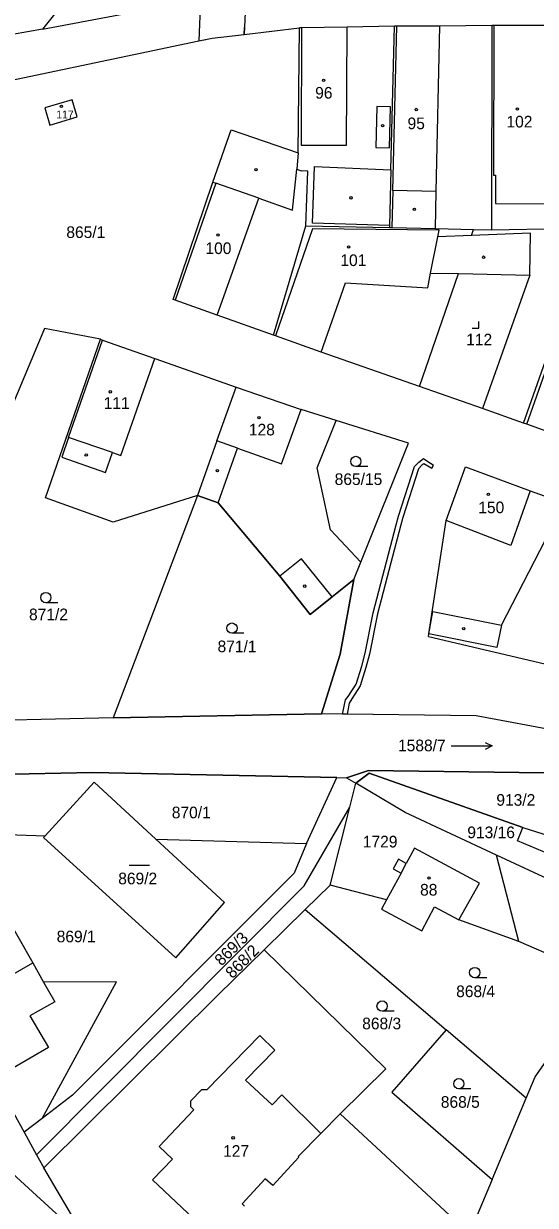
# Model space of a CAD drawing. Extents: x -801826 to -800592, y -1032871 to -1031813.
# Drawn here: x -801007.9 to -800933.1, y -1032553.2 to -1032380.8 of the extents above; entities that cross this region are included whole.
import ezdxf

# ---------------------------------------------------------------- set-up
doc = ezdxf.new("R2010")
doc.units = 0
for name, color, linetype in [('Vrstva 1', 7, 'Continuous'), ('Vrstva 18', 7, 'Continuous'), ('Vrstva 19', 7, 'Continuous'), ('Vrstva 25', 7, 'Continuous'), ('Vrstva 26', 7, 'Continuous'), ('Vrstva 27', 7, 'Continuous'), ('Vrstva 4', 7, 'Continuous')]:
    doc.layers.add(name, color=color, linetype=linetype)

msp = doc.modelspace()

# ---------------------------------------------------------------- linework, layer by layer
at = {"layer": 'Vrstva 1'}
for p, q in [((-800988.54, -1032360.72), (-801005.11, -1032381.61)), ((-801005.11, -1032381.61), (-800982.02, -1032377.22)), ((-801005.11, -1032381.61), (-801018.93, -1032384.07)), ((-800980.34, -1032382.92), (-800975.67, -1032382.37)), ((-800975.67, -1032382.37), (-800967.59, -1032381.42)), ((-800967.74, -1032399.64), (-800967.59, -1032381.42)), ((-800967.29, -1032381.42), (-800967.59, -1032381.42)), ((-800960.59, -1032381.31), (-800967.29, -1032381.42)), ((-800953.67, -1032381.14), (-800960.59, -1032381.31)), ((-800954.21, -1032402.14), (-800953.67, -1032381.14)), ((-800953.37, -1032381.15), (-800953.67, -1032381.14)), ((-800947.06, -1032381.14), (-800953.37, -1032381.15)), ((-800939.48, -1032381.05), (-800947.06, -1032381.14)), ((-800939.48, -1032381.05), (-800939.55, -1032410.87)), ((-800939.18, -1032381.05), (-800939.48, -1032381.05)), ((-800931.09, -1032381.06), (-800939.18, -1032381.05)), ((-801034.47, -1032394.27), (-800982.25, -1032383.32)), ((-800982.25, -1032383.32), (-800980.34, -1032382.92)), ((-801000.76, -1032391.91), (-801004.77, -1032393.09)), ((-801000.02, -1032394.4), (-801000.76, -1032391.91)), ((-801004.77, -1032393.09), (-801004.05, -1032395.59)), ((-801004.05, -1032395.59), (-801000.02, -1032394.4)), ((-800980.21, -1032403.9), (-800977.53, -1032396.3)), ((-800977.53, -1032396.3), (-800967.74, -1032399.64)), ((-800967.74, -1032399.64), (-800967.98, -1032402.01)), ((-800967.98, -1032402.01), (-800967.31, -1032402.26)), ((-800966.33, -1032402.33), (-800967.31, -1032402.26)), ((-800966.66, -1032410.29), (-800966.33, -1032402.33)), ((-800954.21, -1032402.14), (-800954.4, -1032410.24)), ((-800986.01, -1032421.04), (-800980.21, -1032403.9)), ((-800971.37, -1032426.24), (-800966.66, -1032410.29)), ((-800966.66, -1032410.29), (-800954.41, -1032410.53)), ((-800954.4, -1032410.24), (-800954.41, -1032410.53)), ((-800954.41, -1032410.53), (-800954.06, -1032410.54)), ((-800954.06, -1032410.54), (-800947.71, -1032410.69)), ((-800947.71, -1032410.69), (-800942.15, -1032410.81)), ((-800942.45, -1032411.68), (-800942.15, -1032410.81)), ((-800933.82, -1032411.34), (-800942.45, -1032411.68)), ((-800942.15, -1032410.81), (-800939.55, -1032410.87)), ((-800939.55, -1032410.87), (-800925.85, -1032410.64)), ((-800933.94, -1032417.46), (-800933.82, -1032411.34)), ((-800950.04, -1032433.72), (-800944.37, -1032417.25)), ((-800944.37, -1032417.25), (-800933.94, -1032417.46)), ((-800933.94, -1032417.46), (-800940.86, -1032436.95)), ((-800985.73, -1032421.14), (-800986.01, -1032421.04)), ((-800979.58, -1032423.33), (-800985.73, -1032421.14)), ((-800971.37, -1032426.24), (-800979.58, -1032423.33)), ((-801004.8, -1032425.27), (-801028.52, -1032481.63)), ((-800996.61, -1032426.84), (-801004.8, -1032425.27)), ((-801004.67, -1032449.96), (-800996.61, -1032426.84)), ((-800996.61, -1032426.84), (-800996.33, -1032426.94)), ((-800996.33, -1032426.94), (-800988.7, -1032429.66)), ((-800971.09, -1032426.34), (-800971.37, -1032426.24)), ((-800964.38, -1032428.69), (-800971.09, -1032426.34)), ((-800934.84, -1032439.06), (-800930.45, -1032426.67)), ((-800950.04, -1032433.72), (-800964.38, -1032428.69)), ((-800988.7, -1032429.66), (-800976.84, -1032433.83)), ((-800979.63, -1032441.65), (-800976.84, -1032433.83)), ((-800976.84, -1032433.83), (-800967.32, -1032437.08)), ((-800940.86, -1032436.95), (-800950.04, -1032433.72)), ((-800962.22, -1032438.68), (-800967.32, -1032437.08)), ((-800934.84, -1032439.06), (-800940.86, -1032436.95)), ((-800964.97, -1032445.61), (-800962.22, -1032438.68)), ((-800951.67, -1032441.99), (-800962.22, -1032438.68)), ((-800934.37, -1032439.23), (-800934.84, -1032439.06)), ((-800927.67, -1032441.66), (-800934.37, -1032439.23)), ((-800979.63, -1032441.65), (-800982.48, -1032449.6)), ((-800958.63, -1032459.35), (-800951.67, -1032441.99)), ((-800963.05, -1032454.65), (-800964.97, -1032445.61)), ((-800946.15, -1032453.29), (-800943.33, -1032445.44)), ((-800943.33, -1032445.44), (-800933.9, -1032448.93)), ((-800982.48, -1032449.6), (-800994.78, -1032453.49)), ((-800982.48, -1032449.6), (-800994.76, -1032482.06)), ((-800982.48, -1032449.6), (-800994.76, -1032482.06)), ((-800982.48, -1032449.6), (-800979.46, -1032450.68)), ((-800979.46, -1032450.68), (-800982.48, -1032449.6)), ((-800933.9, -1032448.93), (-800928.9, -1032450.72)), ((-800994.78, -1032453.49), (-801004.67, -1032449.96)), ((-800979.46, -1032450.68), (-800970.46, -1032461.4)), ((-800970.46, -1032461.4), (-800979.46, -1032450.68)), ((-800938.09, -1032468.54), (-800928.9, -1032450.72)), ((-800958.63, -1032459.35), (-800963.05, -1032454.65)), ((-800948.66, -1032469.78), (-800946.15, -1032453.29)), ((-800959.63, -1032461.86), (-800958.63, -1032459.35)), ((-800970.46, -1032461.4), (-800966.01, -1032466.96)), ((-800966.01, -1032466.96), (-800970.46, -1032461.4)), ((-800962.82, -1032464.41), (-800959.63, -1032461.86)), ((-800959.63, -1032461.86), (-800962.82, -1032464.41)), ((-800959.63, -1032461.86), (-800961.65, -1032472.78)), ((-800961.65, -1032472.78), (-800959.63, -1032461.86)), ((-800966.01, -1032466.96), (-800962.82, -1032464.41)), ((-800962.82, -1032464.41), (-800966.01, -1032466.96)), ((-800938.09, -1032468.54), (-800938.74, -1032471.78)), ((-800948.73, -1032470.17), (-800948.66, -1032469.78)), ((-800948.73, -1032470.17), (-800927.61, -1032475.17)), ((-800938.74, -1032471.78), (-800948.66, -1032469.78)), ((-800961.65, -1032472.78), (-800964.35, -1032481.48)), ((-800964.35, -1032481.48), (-800961.65, -1032472.78)), ((-800994.76, -1032482.06), (-801024.5, -1032482.76)), ((-800994.76, -1032482.06), (-801024.5, -1032482.76)), ((-800964.35, -1032481.48), (-800994.76, -1032482.06)), ((-800994.76, -1032482.06), (-800964.35, -1032481.48)), ((-800964.35, -1032481.48), (-800994.76, -1032482.06)), ((-800941.77, -1032481.76), (-800964.35, -1032481.48)), ((-800961.28, -1032481.52), (-800964.35, -1032481.48)), ((-800941.77, -1032481.76), (-800960.62, -1032481.53)), ((-800920.07, -1032485.78), (-800941.77, -1032481.76)), ((-800920.07, -1032485.78), (-800941.77, -1032481.76)), ((-800997.78, -1032490.01), (-801020.2, -1032490.51)), ((-801020.2, -1032490.51), (-800997.78, -1032490.01)), ((-800962.1, -1032490.76), (-800997.78, -1032490.01)), ((-800997.78, -1032490.01), (-800962.1, -1032490.76)), ((-800966.57, -1032500.41), (-800962.1, -1032490.76)), ((-800962.1, -1032490.76), (-800960.71, -1032490.83)), ((-800962.1, -1032490.76), (-800960.71, -1032490.83)), ((-800957.47, -1032489.74), (-800960.71, -1032490.83)), ((-800957.47, -1032489.74), (-800960.71, -1032490.83)), ((-800960.71, -1032490.83), (-800957.47, -1032489.74)), ((-800960.71, -1032490.83), (-800959.34, -1032491.58)), ((-800960.71, -1032490.83), (-800959.34, -1032491.58)), ((-800957.38, -1032490.12), (-800959.34, -1032491.58)), ((-800959.34, -1032491.58), (-800957.38, -1032490.12)), ((-800931.84, -1032490.09), (-800957.47, -1032489.74)), ((-800931.84, -1032490.09), (-800957.47, -1032489.74)), ((-800957.47, -1032489.74), (-800931.84, -1032490.09)), ((-800934.97, -1032498.07), (-800957.38, -1032490.12)), ((-800957.38, -1032490.12), (-800934.97, -1032498.07)), ((-800997.57, -1032491.42), (-801004.72, -1032499.25)), ((-800988.55, -1032499.75), (-800997.57, -1032491.42)), ((-800960.22, -1032495.07), (-800959.34, -1032491.58)), ((-800952.14, -1032495.84), (-800959.34, -1032491.58)), ((-800966.87, -1032506.55), (-800960.22, -1032495.07)), ((-800963.1, -1032506.46), (-800960.22, -1032495.07)), ((-800938.81, -1032502.08), (-800952.14, -1032495.84)), ((-801017.33, -1032498.87), (-801006.53, -1032517.81)), ((-801017.33, -1032498.87), (-801004.72, -1032499.25)), ((-801004.72, -1032499.25), (-801004.96, -1032499.52)), ((-801004.96, -1032499.52), (-800985.65, -1032517.05)), ((-800935.72, -1032499.98), (-800934.97, -1032498.07)), ((-800934.97, -1032498.07), (-800914.08, -1032504.56)), ((-800934.97, -1032498.07), (-800914.08, -1032504.56)), ((-800978.54, -1032508.99), (-800988.55, -1032499.75)), ((-800988.55, -1032499.75), (-800966.57, -1032500.41)), ((-800966.57, -1032500.41), (-800968.36, -1032504.73)), ((-800950.77, -1032501.05), (-800951.97, -1032503.29)), ((-800941.3, -1032506.19), (-800950.77, -1032501.05)), ((-800917.44, -1032507.8), (-800935.72, -1032499.98)), ((-800953.11, -1032502.68), (-800953.88, -1032504.08)), ((-800951.97, -1032503.29), (-800953.11, -1032502.68)), ((-800935.54, -1032514.69), (-800938.81, -1032502.08)), ((-800918.13, -1032511.75), (-800938.81, -1032502.08)), ((-800968.36, -1032504.73), (-801000.73, -1032537.11)), ((-800952.73, -1032504.7), (-800954.86, -1032508.62)), ((-800953.88, -1032504.08), (-800952.73, -1032504.7)), ((-800966.72, -1032510), (-800963.1, -1032506.46)), ((-800954.86, -1032508.62), (-800963.1, -1032506.46)), ((-800944.3, -1032511.52), (-800941.3, -1032506.19)), ((-801005.96, -1032545.81), (-800966.87, -1032506.55)), ((-800985.65, -1032517.05), (-800978.54, -1032508.99)), ((-800954.86, -1032508.62), (-800955.58, -1032509.95)), ((-800955.58, -1032509.95), (-800949.72, -1032513.13)), ((-800949.72, -1032513.13), (-800947.86, -1032509.62)), ((-800947.86, -1032509.62), (-800944.3, -1032511.52)), ((-800972.75, -1032515.92), (-800966.72, -1032510)), ((-800966.72, -1032510), (-800946.16, -1032527.55)), ((-800935.54, -1032514.69), (-800944.3, -1032511.52)), ((-800921.99, -1032520.58), (-800935.54, -1032514.69)), ((-800979.44, -1032522.46), (-800972.75, -1032515.92)), ((-800972.75, -1032515.92), (-800954.98, -1032533.26)), ((-801006.53, -1032517.81), (-801004.95, -1032520.59)), ((-801005.17, -1032540.51), (-800994.31, -1032520.55)), ((-800994.31, -1032520.55), (-801004.95, -1032520.59)), ((-801004.92, -1032547.69), (-800979.44, -1032522.46)), ((-800933.15, -1032534.42), (-800927.7, -1032526.63)), ((-800946.16, -1032527.55), (-800954.1, -1032536.64)), ((-800934.45, -1032537.55), (-800946.16, -1032527.55)), ((-800954.98, -1032533.26), (-800961.62, -1032539.82)), ((-801012.11, -1032534.69), (-801007.79, -1032542.51)), ((-800934.45, -1032537.55), (-800933.15, -1032534.42)), ((-801000.73, -1032537.11), (-801005.17, -1032540.51)), ((-800954.1, -1032536.64), (-800939.42, -1032549.38)), ((-800939.42, -1032549.38), (-800934.45, -1032537.55)), ((-801005.17, -1032540.51), (-801007.79, -1032542.51)), ((-800961.62, -1032539.82), (-800964.47, -1032542.7)), ((-800961.62, -1032539.82), (-800942.75, -1032557.29)), ((-801007.79, -1032542.51), (-801005.96, -1032545.81)), ((-800964.47, -1032542.7), (-800967.78, -1032546.04)), ((-801005.96, -1032545.81), (-801004.92, -1032547.69)), ((-800967.67, -1032546.14), (-800971.47, -1032550.29)), ((-800967.78, -1032546.04), (-800967.67, -1032546.14)), ((-800998.43, -1032558.61), (-801010.64, -1032547.43)), ((-800998.43, -1032558.61), (-801004.92, -1032547.69)), ((-800972.56, -1032549.29), (-800975.93, -1032552.97)), ((-800971.47, -1032550.29), (-800972.56, -1032549.29)), ((-800939.42, -1032549.38), (-800942.75, -1032557.29)), ((-800975.93, -1032552.97), (-800975.6, -1032553.27))]:
    msp.add_line(p, q, dxfattribs=at)
for points in [[(-800960.62, -1032481.53), (-800960.62, -1032481.53), (-800961.28, -1032481.52)], [(-800961.28, -1032481.52), (-800961.28, -1032481.52)]]:
    msp.add_lwpolyline(points, dxfattribs=at)
at = {"layer": 'Vrstva 25'}
for p, q in [((-800942.36, -1032425.22), (-800941.36, -1032425.22)), ((-800941.36, -1032425.22), (-800941.36, -1032424.22)), ((-800957.59, -1032445.4), (-800959.34, -1032445.4)), ((-801002.86, -1032465.27), (-801004.61, -1032465.27)), ((-800975.68, -1032469.72), (-800977.43, -1032469.72)), ((-800945.43, -1032486.16), (-800939.43, -1032486.16)), ((-800992.46, -1032503.57), (-800989.46, -1032503.57)), ((-800940.23, -1032519.97), (-800941.98, -1032519.97)), ((-800953.75, -1032524.85), (-800955.5, -1032524.85)), ((-800942.55, -1032536.17), (-800944.3, -1032536.17))]:
    msp.add_line(p, q, dxfattribs=at)
msp.add_lwpolyline([(-800940.43, -1032485.66), (-800939.43, -1032486.16), (-800940.43, -1032486.66)], dxfattribs=at)
for centre, radius in [((-800964.04, -1032389.08), 0.175), ((-801002.34, -1032392.87), 0.175), ((-800950.51, -1032393.32), 0.175), ((-800935.74, -1032393.26), 0.175), ((-800955.44, -1032395.68), 0.175), ((-800973.94, -1032402.08), 0.175), ((-800960.05, -1032406.2), 0.175), ((-800950.79, -1032407.87), 0.175), ((-800979.48, -1032411.64), 0.175), ((-800960.39, -1032413.37), 0.175), ((-800940.69, -1032414.86), 0.175), ((-800995.2, -1032434.5), 0.175), ((-800973.5, -1032438.28), 0.175), ((-800998.72, -1032443.7), 0.175), ((-800959.34, -1032444.65), 0.75), ((-800979.55, -1032446.01), 0.175), ((-800939.98, -1032449.46), 0.175), ((-800966.81, -1032462.85), 0.175), ((-801004.61, -1032464.52), 0.75), ((-800977.43, -1032468.97), 0.75), ((-800943.59, -1032469.06), 0.175), ((-800948.65, -1032505.4), 0.175), ((-800941.98, -1032519.22), 0.75), ((-800955.5, -1032524.1), 0.75), ((-800944.3, -1032535.42), 0.75), ((-800977.26, -1032543.32), 0.175)]:
    msp.add_circle(centre, radius, dxfattribs=at)
at = {"layer": 'Vrstva 26'}
for p, q in [((-800975.67, -1032382.37), (-800975.62, -1032381.37)), ((-800982.25, -1032383.32), (-800981.27, -1032383.12))]:
    msp.add_line(p, q, dxfattribs=at)
at = {"layer": 'Vrstva 27'}
msp.add_lwpolyline([(-800961.28, -1032481.52), (-800960.86, -1032479.44), (-800960.48, -1032478.95), (-800959.29, -1032477.14), (-800958.48, -1032474.53), (-800957.96, -1032472.61), (-800956.8, -1032466.72), (-800954.84, -1032459.28), (-800953.44, -1032453.92), (-800953.1, -1032452.65), (-800950.76, -1032445.41), (-800950.16, -1032444.75), (-800949.47, -1032444.24), (-800948.82, -1032444.66), (-800948.04, -1032445.13), (-800948.25, -1032445.7), (-800949.43, -1032444.98), (-800949.72, -1032445.19), (-800950.2, -1032445.72), (-800952.5, -1032452.82), (-800952.83, -1032454.08), (-800954.24, -1032459.43), (-800956.18, -1032466.87), (-800957.35, -1032472.75), (-800957.88, -1032474.71), (-800958.71, -1032477.4), (-800959.93, -1032479.26), (-800960.3, -1032479.91), (-800960.62, -1032481.53), (-800961.28, -1032481.52)], dxfattribs=at)
at = {"layer": 'Vrstva 4'}
for p, q in [((-800975.27, -1032373.92), (-800975.67, -1032382.37)), ((-800982.02, -1032377.22), (-800982.25, -1032383.32)), ((-800967.29, -1032381.42), (-800967.31, -1032398.52)), ((-800960.71, -1032398.53), (-800960.59, -1032381.31)), ((-800953.93, -1032405.14), (-800953.37, -1032381.15)), ((-800947.63, -1032405.29), (-800947.06, -1032381.14)), ((-800939.18, -1032381.05), (-800939.23, -1032402.91)), ((-800956.29, -1032392.88), (-800956.43, -1032398.88)), ((-800954.3, -1032392.93), (-800956.29, -1032392.88)), ((-800954.44, -1032398.93), (-800954.3, -1032392.93)), ((-800967.31, -1032398.52), (-800960.71, -1032398.53)), ((-800956.43, -1032398.88), (-800954.44, -1032398.93)), ((-800968.57, -1032407.98), (-800967.98, -1032402.01)), ((-800965.65, -1032409.9), (-800965.4, -1032401.62)), ((-800965.4, -1032401.62), (-800954.21, -1032402.14)), ((-800939.23, -1032402.91), (-800938.93, -1032402.91)), ((-800938.93, -1032402.91), (-800938.94, -1032407.04)), ((-800979.79, -1032404.05), (-800985.73, -1032421.14)), ((-800980.21, -1032403.9), (-800979.79, -1032404.05)), ((-800973.51, -1032406.23), (-800979.79, -1032404.05)), ((-800979.58, -1032423.33), (-800973.51, -1032406.23)), ((-800973.51, -1032406.23), (-800968.57, -1032407.98)), ((-800953.93, -1032405.14), (-800954.06, -1032410.54)), ((-800947.63, -1032405.29), (-800953.93, -1032405.14)), ((-800947.71, -1032410.69), (-800947.63, -1032405.29)), ((-800938.94, -1032407.04), (-800930.83, -1032407.06)), ((-800954.4, -1032410.24), (-800965.65, -1032409.9)), ((-800965.66, -1032410.7), (-800971.09, -1032426.34)), ((-800947.16, -1032410.9), (-800965.66, -1032410.7)), ((-800947.36, -1032411.88), (-800947.16, -1032410.9)), ((-800942.45, -1032411.68), (-800947.36, -1032411.88)), ((-800948.42, -1032417.17), (-800947.36, -1032411.88)), ((-800948.85, -1032419.33), (-800948.42, -1032417.17)), ((-800948.42, -1032417.17), (-800944.37, -1032417.25)), ((-800964.38, -1032428.69), (-800960.83, -1032418.6)), ((-800960.83, -1032418.6), (-800948.85, -1032419.33)), ((-801001.29, -1032441.18), (-800996.33, -1032426.94)), ((-800934.37, -1032439.23), (-800929.98, -1032426.83)), ((-800993.66, -1032443.78), (-800988.7, -1032429.66)), ((-800970.21, -1032445), (-800967.32, -1032437.08)), ((-801001.29, -1032441.18), (-801002.29, -1032444.05)), ((-800994.88, -1032443.36), (-801001.29, -1032441.18)), ((-800976.62, -1032442.72), (-800979.63, -1032441.65)), ((-800979.46, -1032450.68), (-800976.62, -1032442.72)), ((-800976.62, -1032442.72), (-800970.21, -1032445)), ((-801002.29, -1032444.05), (-800995.9, -1032446.27)), ((-800995.9, -1032446.27), (-800994.88, -1032443.36)), ((-800994.88, -1032443.36), (-800993.66, -1032443.78)), ((-800933.9, -1032448.93), (-800936.72, -1032456.9)), ((-800936.72, -1032456.9), (-800946.15, -1032453.29)), ((-800967.27, -1032458.85), (-800970.46, -1032461.4)), ((-800962.82, -1032464.41), (-800967.27, -1032458.85)), ((-800948.66, -1032469.78), (-800948.09, -1032466.53)), ((-800948.09, -1032466.53), (-800938.09, -1032468.54)), ((-800952.73, -1032504.7), (-800951.97, -1032503.29)), ((-801018.01, -1032524.35), (-801006.53, -1032517.81)), ((-801004.95, -1032520.59), (-801003.31, -1032523.46)), ((-801003.31, -1032523.46), (-801006.96, -1032525.54)), ((-801006.96, -1032525.54), (-801004.24, -1032530.12)), ((-800973.35, -1032528.4), (-800981.09, -1032536.34)), ((-800973.35, -1032528.4), (-800971.17, -1032530.52)), ((-801004.24, -1032530.12), (-801012.11, -1032534.69)), ((-800971.17, -1032530.52), (-800975.45, -1032534.91)), ((-800975.45, -1032534.91), (-800971.56, -1032538.49)), ((-800983.46, -1032537.9), (-800981.89, -1032536.3)), ((-800981.09, -1032536.34), (-800981.89, -1032536.3)), ((-800971.56, -1032538.49), (-800970.15, -1032537.07)), ((-800970.15, -1032537.07), (-800964.47, -1032542.7)), ((-800988.05, -1032544.58), (-800983, -1032539.23)), ((-800983.43, -1032538.82), (-800983.46, -1032537.9)), ((-800983, -1032539.23), (-800983.43, -1032538.82)), ((-800988.05, -1032544.58), (-800986.1, -1032546.45)), ((-800986.1, -1032546.45), (-800989.02, -1032549.47)), ((-800989.02, -1032549.47), (-800982.17, -1032555.91))]:
    msp.add_line(p, q, dxfattribs=at)

# ---------------------------------------------------------------- texts
at = {"layer": 'Vrstva 18'}
for s, p in [('865/1', (-801001.62, -1032412.06)), ('865/15', (-800962.43, -1032448.09)), ('871/2', (-801007.07, -1032467.82)), ('871/1', (-800979.53, -1032472.48)), ('1588/7', (-800953.18, -1032486.93)), ('913/2', (-800938.82, -1032494.88)), ('870/1', (-800986.22, -1032496.71)), ('913/16', (-800943.06, -1032499.61)), ('1729', (-800958.32, -1032500.96)), ('869/2', (-800994.04, -1032506.34)), ('869/1', (-801003.03, -1032514.8)), ('868/4', (-800944.69, -1032522.8)), ('868/3', (-800958.41, -1032527.49)), ('868/5', (-800946.93, -1032538.94))]:
    msp.add_text(s, height=1.7, dxfattribs=at).set_placement(p)
for s, rotation, p in [('869/3', 44.6817, (-800978.96, -1032518.34)), ('868/2', 44.8724, (-800977.37, -1032520.19))]:
    msp.add_text(s, height=1.7, rotation=rotation, dxfattribs=at).set_placement(p)
at = {"layer": 'Vrstva 19'}
for s, height, p in [('96', 1.7, (-800965.28, -1032391.73)), ('117', 1.14, (-801003.09, -1032394.61)), ('95', 1.7, (-800951.79, -1032396.19)), ('102', 1.7, (-800937.34, -1032395.94)), ('100', 1.7, (-800981.3, -1032414.4)), ('101', 1.7, (-800961.6, -1032416.15)), ('112', 1.7, (-800943.22, -1032427.73)), ('111', 1.7, (-800996.17, -1032436.98)), ('128', 1.7, (-800974.96, -1032440.86)), ('150', 1.7, (-800941.46, -1032452.21)), ('88', 1.7, (-800949.96, -1032507.98)), ('127', 1.7, (-800978.73, -1032546.09))]:
    msp.add_text(s, height=height, dxfattribs=at).set_placement(p)

doc.saveas('drawing.dxf')
